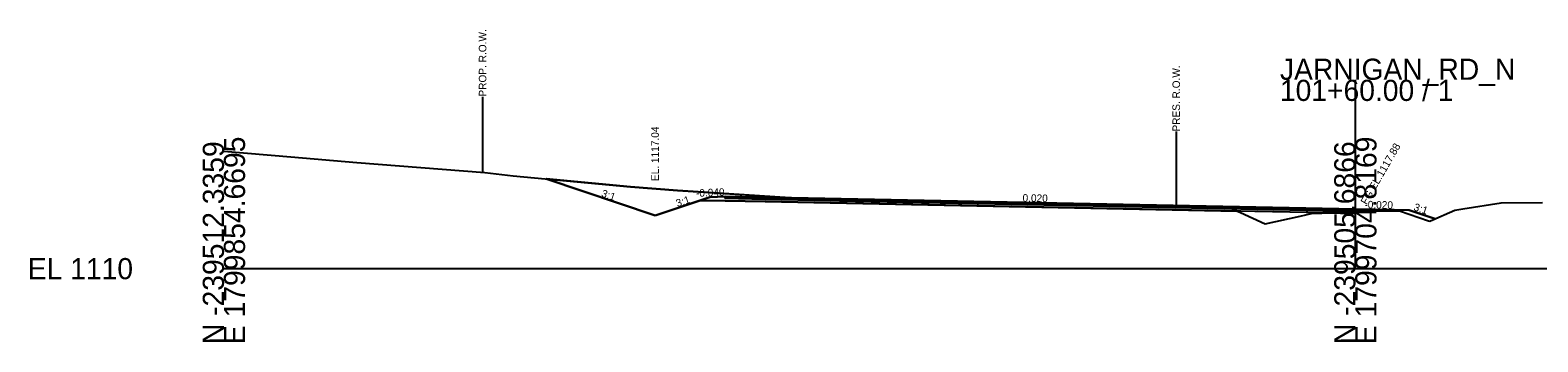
# Model space of a CAD drawing. Extents: x 214513 to 217151, y 214739 to 216780.
# Drawn here: x 216122.7 to 216322.6, y 215238.7 to 215279.9 of the extents above; entities that cross this region are included whole.
import ezdxf

# ---------------------------------------------------------------- set-up
doc = ezdxf.new("R2010")
doc.units = 0
for name, color, linetype in [('CONCEPT - TRANSPORTATION - Roads Text', 7, 'Continuous'), ('DESIGN - CENTERLINE - Proposed', 7, 'Continuous'), ('DESIGN - CENTERLINE - Proposed Text', 7, 'Continuous'), ('DESIGN - DRAINAGE - Special Ditches', 7, 'Continuous'), ('DESIGN - EARTHWORK - Shapes', 7, 'Continuous'), ('DESIGN - ROW - Right-of-Way Linework', 7, 'Continuous'), ('DESIGN - TRANSPORTATION - Text', 7, 'Continuous'), ('DESIGN - TYPICAL - Slope Tie Text', 7, 'Continuous'), ('Section', 7, 'Continuous'), ('SURVEY - DTM GRAPHICS - Triangles', 7, 'Continuous'), ('SURVEY - PROPERTY - ROW Lines', 7, 'Continuous'), ('XSCell', 7, 'Continuous')]:
    doc.layers.add(name, color=color, linetype=linetype)

msp = doc.modelspace()

# ---------------------------------------------------------------- linework, layer by layer
at = {"layer": 'DESIGN - DRAINAGE - Special Ditches'}
for points in [[(216205.52, 215255.41), (216191.07, 215260.23)], [(216214.83, 215257.92), (216214.83, 215257.67), (216220.12, 215257.56), (216298.36, 215255.99), (216298.36, 215255.66), (216220.12, 215257.23), (216214.83, 215257.34), (216211.5, 215257.4), (216212.8, 215257.83), (216214.83, 215257.92)], [(216298.36, 215256.24), (216214.83, 215257.92), (216214.83, 215257.82), (216214.83, 215257.82), (216298.36, 215256.14), (216298.36, 215256.14), (216298.36, 215256.14), (216298.36, 215256.24), (216298.36, 215256.24)], [(216212.8, 215257.83), (216205.52, 215255.41)], [(216298.36, 215256.14), (216214.83, 215257.82), (216214.83, 215257.67), (216214.83, 215257.67), (216298.36, 215255.99), (216298.36, 215255.99), (216298.36, 215255.99), (216298.36, 215256.14), (216298.36, 215256.14)], [(216298.36, 215256.24), (216298.36, 215256.24), (216298.36, 215256.14), (216298.36, 215256.14), (216298.36, 215256.14), (216303.49, 215256.04), (216303.49, 215256.04), (216303.49, 215256.14), (216298.36, 215256.24)], [(216303.49, 215256.14), (216305.51, 215256.1)], [(216305.51, 215256.1), (216308.93, 215254.96)]]:
    msp.add_lwpolyline(points, dxfattribs=at)
at = {"layer": 'DESIGN - EARTHWORK - Shapes'}
for p, q in [((216191.07, 215260.23), (216205.52, 215255.41)), ((216214.83, 215257.92), (216223.44, 215257.74)), ((216223.44, 215257.74), (216214.83, 215257.92)), ((216205.52, 215255.41), (216211.5, 215257.4)), ((216214.83, 215257.82), (216214.83, 215257.67)), ((216225.75, 215257.6), (216214.83, 215257.82)), ((216220.12, 215257.56), (216214.83, 215257.67)), ((216214.83, 215257.67), (216220.12, 215257.56)), ((216229.22, 215257.38), (216220.12, 215257.56)), ((216220.12, 215257.56), (216229.22, 215257.38)), ((216225.75, 215257.6), (216223.44, 215257.74)), ((216229.22, 215257.38), (216225.75, 215257.6)), ((216281.41, 215256.33), (216247.32, 215257.02)), ((216247.32, 215257.02), (216281.41, 215256.33)), ((216294.41, 215255.74), (216282.7, 215255.98)), ((216298.36, 215255.95), (216294.41, 215255.74)), ((216298.36, 215256.14), (216298.36, 215255.99)), ((216298.36, 215255.99), (216298.36, 215255.95)), ((216298.36, 215255.66), (216298.36, 215255.95)), ((216305.51, 215256.1), (216303.49, 215256.14)), ((216308.93, 215254.96), (216305.51, 215256.1)), ((216294.41, 215255.74), (216298.36, 215255.66))]:
    msp.add_line(p, q, dxfattribs=at)
for points in [[(216223.44, 215257.74), (216209.2, 215258.64), (216208.48, 215258.7), (216202.25, 215259.19), (216191.07, 215260.23)], [(216211.5, 215257.4), (216212.8, 215257.83), (216214.83, 215257.92)], [(216214.83, 215257.67), (216214.83, 215257.82), (216214.83, 215257.92), (216212.8, 215257.83), (216211.5, 215257.4), (216214.83, 215257.34), (216220.12, 215257.23), (216282.7, 215255.98)], [(216214.83, 215257.92), (216214.83, 215257.82), (216225.75, 215257.6)], [(216247.32, 215257.02), (216238.38, 215257.14), (216229.99, 215257.33), (216229.22, 215257.38)], [(216281.41, 215256.33), (216281.07, 215256.36), (216271.45, 215256.59), (216263.66, 215256.73), (216248.21, 215257), (216247.32, 215257.02)], [(216282.7, 215255.98), (216282.02, 215256.29), (216281.41, 215256.33)], [(216282.7, 215255.98), (216283.14, 215255.77), (216286.39, 215254.28), (216291.03, 215255.29), (216292.54, 215255.67), (216293.91, 215255.72), (216294.41, 215255.74)], [(216303.49, 215256.14), (216303.49, 215256.04), (216298.36, 215256.14)], [(216298.36, 215255.95), (216298.63, 215255.96), (216300.57, 215255.96), (216304.19, 215256.03), (216308.06, 215254.7), (216308.22, 215254.65), (216308.3, 215254.68), (216308.93, 215254.96)]]:
    msp.add_lwpolyline(points, dxfattribs=at)
at = {"layer": 'DESIGN - ROW - Right-of-Way Linework'}
msp.add_lwpolyline([(216182.65, 215271.12), (216182.65, 215261.12)], dxfattribs=at)
at = {"layer": 'SURVEY - DTM GRAPHICS - Triangles'}
msp.add_lwpolyline([(216148.36, 215263.92), (216157.24, 215263.15), (216165.98, 215262.43), (216182.95, 215261.1), (216186.7, 215260.63), (216202.25, 215259.19), (216208.48, 215258.7), (216209.2, 215258.64), (216229.99, 215257.33), (216238.38, 215257.14), (216248.21, 215257), (216263.66, 215256.73), (216271.45, 215256.59), (216281.07, 215256.36), (216282.02, 215256.29), (216283.14, 215255.77), (216286.39, 215254.28), (216291.03, 215255.29), (216292.54, 215255.67), (216293.91, 215255.72), (216298.63, 215255.96), (216300.57, 215255.96), (216304.19, 215256.03), (216308.06, 215254.7), (216308.22, 215254.65), (216308.3, 215254.68), (216311.53, 215256.12), (216312.63, 215256.28), (216317.7, 215257.06), (216323.15, 215257.12)], dxfattribs=at)
at = {"layer": 'SURVEY - PROPERTY - ROW Lines'}
msp.add_lwpolyline([(216274.61, 215266.51), (216274.61, 215256.51)], dxfattribs=at)
at = {"layer": 'XSCell'}
for p, q in [((216298.36, 215248.36), (216298.36, 215273.36)), ((216148.36, 215248.36), (216298.36, 215248.36)), ((216298.36, 215248.36), (216448.36, 215248.36))]:
    msp.add_line(p, q, dxfattribs=at)

# ---------------------------------------------------------------- texts
at = {"layer": 'CONCEPT - TRANSPORTATION - Roads Text'}
for s, rotation, p in [('-0.040', 2.2906, (216210.96, 215257.86)), ('0.020', 358.8542, (216254.23, 215257.23)), ('-0.020', 358.8542, (216299.55, 215256.35))]:
    msp.add_text(s, height=1, rotation=rotation, dxfattribs=at).set_placement(p)
at = {"layer": 'DESIGN - CENTERLINE - Proposed'}
msp.add_text('EL. 1117.04', height=1, rotation=90, dxfattribs=at).set_placement((216206.02, 215259.96))
at = {"layer": 'DESIGN - CENTERLINE - Proposed Text'}
msp.add_text('FG EL.1117.88', height=1, rotation=60, dxfattribs=at).set_placement((216299.86, 215256.74))
at = {"layer": 'DESIGN - TRANSPORTATION - Text'}
for s, p in [('PROP. R.O.W.', (216183.15, 215271.14)), ('PRES. R.O.W.', (216275.11, 215266.51))]:
    msp.add_text(s, height=1, rotation=90, dxfattribs=at).set_placement(p)
at = {"layer": 'DESIGN - TYPICAL - Slope Tie Text'}
for rotation, p in [(341.5651, (216198.32, 215257.91)), (18.4349, (216208.48, 215256.5)), (341.5652, (216306.01, 215256.1))]:
    msp.add_text('3:1', height=1, rotation=rotation, dxfattribs=at).set_placement(p)
at = {"layer": 'Section'}
msp.add_text('-', height=0.0001, dxfattribs=at).set_placement((216148.36, 215248.36))
at = {"layer": 'XSCell'}
for s, p in [('JARNIGAN_RD_N', (216288.36, 215273.36)), ('101+60.00 / 1', (216288.36, 215270.56)), ('EL 1110', (216122.36, 215246.96))]:
    msp.add_text(s, height=2.8, dxfattribs=at).set_placement(p)
for s, p in [('N -239512.3359', (216148.36, 215238.36)), ('E 1799854.6695', (216151.16, 215238.36)), ('N -239505.6866', (216298.36, 215238.36)), ('E 1799704.8169', (216301.16, 215238.36))]:
    msp.add_text(s, height=2.8, rotation=90, dxfattribs=at).set_placement(p)

doc.saveas('drawing.dxf')
